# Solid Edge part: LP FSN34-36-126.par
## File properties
Title: Locating Pin
Author: Dan
Template: Locating Pin.par
Last saved by: Dan
Revision: 6
Application: Solid Edge
Density: 0.000007833 kg/mm^3
Accuracy: 0.99
Document Number: GC
Material: Steel
Face Style: Steel
Fill Style: ANSI32(Steel)
Virtual Style: Machined steel
Coef. of Thermal Exp: 1.3e-05
Thermal Conductivity: 32.0
Specific Heat: 481.0
Modulus of Elasticity: 199947953000.0
Poisson's Ratio: 0.29
Yield Stress: 262000766.0
Ultimate Stress: 358527364.0
Elongation: 0.0
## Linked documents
FSN34-36-126.par
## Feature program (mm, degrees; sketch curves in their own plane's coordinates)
part copy "CopiedPart_1"
Other named dimensions: "Face_Move_1": Distance = 10 mm
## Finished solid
Body 1: solid body, 8 faces, 7 edges, 0 vertices.
  Faces by surface: plane 4, cylinder 3, cone 1
  Edges by curve: circle 7
Bounding box of the edges (mm): 162.000 x 46.000 x 46.000, from (0, -23, -23) to (162, 23, 23).
Cylindrical faces by radius (mm): R17 x1, R21 x1, R23 x1
Conical faces (half-angle, radius in mm at the cone's reference point): 15 deg R17 x1
Planar faces by outward normal: +x 3, -x 1
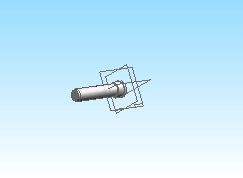
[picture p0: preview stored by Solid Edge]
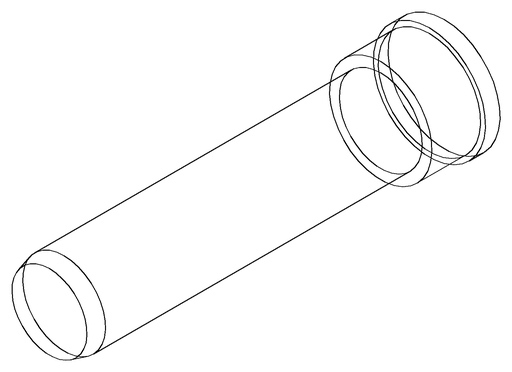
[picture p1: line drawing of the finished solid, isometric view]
